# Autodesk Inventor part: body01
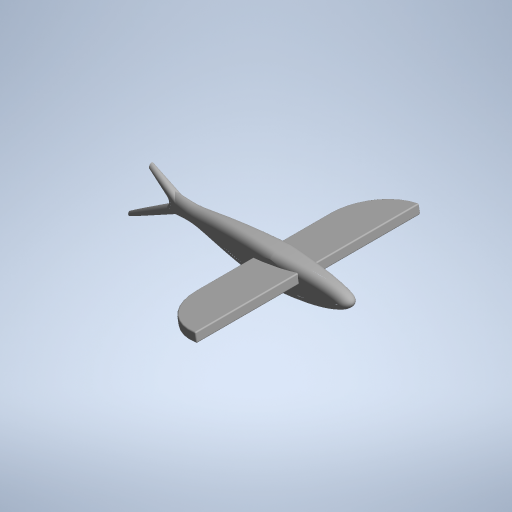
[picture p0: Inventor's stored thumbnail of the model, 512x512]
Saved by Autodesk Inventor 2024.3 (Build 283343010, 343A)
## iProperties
Created: 2018-12
Part Number: body01
Material: 一般
Document SubType Name: モデリング
Designer: Kikut
Appearance: 一般
Author: Kikut
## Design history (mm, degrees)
sketch "スケッチ1"
  geometry: L1 (-60, 8)-(-60, -10); 8 further points
  constraints: 2 end point, 9 other
  dimensions: "d0" = 100 distance of point (0, 0) point (100, 0); "d1" = 60 horizontal distance of L1.end point (0, 0); "d2" = 0 horizontal distance of L1.end L1.start; "d3" = 0 horizontal distance of point (-38, -8) point (-38, 6); "d4" = 14 horizontal distance of point (-14, -12) point (0, 0); "d5" = 24 horizontal distance of point (-38, -8) point (-14, -12); "d6" = 20 horizontal distance of point (-20, 8) point (0, 0); "d7" = 30 horizontal distance of point (70, -14) point (100, 0); "d8" = 34 horizontal distance of point (100, 0) point (66, 10); "d9" = 10 vertical distance of point (100, 0) point (66, 10); "d10" = 0 vertical distance of point (0, 0) point (100, 0); "d11" = 14 vertical distance of point (70, -14) point (100, 0); "d12" = 8 vertical distance of point (0, 0) point (-20, 8); "d13" = 12 vertical distance of point (-14, -12) point (0, 0); "d14" = 8 vertical distance of point (-38, -8) point (0, 0); "d15" = 10 vertical distance of L1.end point (0, 0); "d16" = 8 vertical distance of L1.start point (0, 0); "d17" = 6 vertical distance of point (-38, 6) point (0, 0)
extrude "押し出し1" new body sketch "スケッチ1" stored distance "d29" = 20; taper "d30" = 0 deg
sketch "スケッチ6"
  geometry: L1 (-18, 20)-(0, 20); L2 (0, 20)-(0, 0); L3 (0, 0)-(-18, 0); L4 (-18, 0)-(-18, 20); 1 further point
  constraints: 8 end point, 2 parallel, 1 horizontal, 1 perpendicular
extrude "押し出し6" join sketch "スケッチ6" distance "d59" = 40; taper "d60" = 30 deg
sketch "スケッチ7"
  geometry: L1 (-50, 11)-(30, 11); L2 (30, 11)-(30, 51); L3 (30, 51)-(-50, 51); L4 (-50, 51)-(-50, 11); 1 further point
  constraints: 8 end point, 2 parallel, 1 horizontal, 1 perpendicular
  dimensions: "d61" = 40 distance from line of point (-10, 10) L4; "d62" = 80 distance of L2.end L3.end; "d63" = 40 distance of L3.end L1.start; "d64" = 1 distance from line of L1 point (-10, 10)
extrude "押し出し7" cut sketch "スケッチ7" extent not by distance; stored distance "d65" = 40; taper "d66" = -4 deg
sketch "スケッチ8"
  geometry: L1 (-50, -31)-(30, -31); L2 (30, -31)-(30, 9); L3 (30, 9)-(-50, 9); L4 (-50, 9)-(-50, -31); 1 further point
  constraints: 8 end point, 2 parallel, 1 horizontal, 1 perpendicular
  dimensions: "d67" = 1 distance from line of point (-10, 10) L3; "d68" = 40 distance of L3.end L1.start; "d69" = 40 distance from line of point (-10, 10) L4; "d70" = 80 distance of L1.start L1.end
extrude "押し出し8" cut sketch "スケッチ8" extent not by distance; stored distance "d71" = 40; taper "d72" = -4 deg
sketch "スケッチ9" dims "d130" = 3
  geometry: L1 (-40, 30)-(20, 30); L2 (20, 30)-(20, 60); L3 (20, 60)-(-40, 60); L4 (-40, 60)-(-40, 30); 1 further point
  constraints: 8 end point, 2 parallel, 1 horizontal, 1 perpendicular
  dimensions: "d73" = 20 distance from line of L1 point (-10, 10); "d74" = 30 distance of L3.end L1.start; "d75" = 30 distance from line of point (-10, 10) L4; "d76" = 60 distance of L2.end L3.end
extrude "押し出し9" cut sketch "スケッチ9" extent not by distance; stored distance "d77" = 0; taper "d78" = 4 deg
sketch "スケッチ10"
  geometry: L1 (-40, -40)-(20, -40); L2 (20, -40)-(20, -10); L3 (20, -10)-(-40, -10); L4 (-40, -10)-(-40, -40); L5 (-41.094, 9)-(23.094, 9) reference; 3 further points
  constraints: 8 end point, 2 parallel, 1 horizontal, 1 perpendicular
  dimensions: "d80" = 30 distance of L3.end L1.start; "d81" = 30 distance from line of point (-10, 10) L4; "d82" = 60 distance of L1.start L1.end; "d85" = 20 distance from line of L3 point (-10, 10)
extrude "押し出し10" cut sketch "スケッチ10" extent not by distance; stored distance "d83" = 0; taper "d84" = 4 deg
fillet "フィレット8" dims "d100" = 6
fillet "フィレット9" dims "d101" = 6
sketch "スケッチ14"
  geometry: L1 (62, 1)-(62, -3); L2 (62, -3)-(112.078, -35); L3 (112.078, -35)-(112.078, 37); L4 (112.078, 37)-(62, 1); L5 (112.078, 37)-(112.078, 47); L6 (112.078, 47)-(80.078, 23.996); L7 (80.078, 23.996)-(80.078, 13.996); L8 (80.078, 13.996)-(112.078, 37); 1 further point
  constraints: 16 end point, 2 parallel, 2 vertical, 1 collinear, 1 point on line
  dimensions: "d119" = 62 distance from line of L1 point (0, 0); "d120" = 1 vertical distance of point (0, 0) L1.start; "d121" = 3 vertical distance of L1.end point (0, 0); "d122" = 36 vertical distance of L3.end L1.start; "d123" = 32 vertical distance of L2.end L1.end; "d124" = 10 distance of L3.end L5.end; "d125" = 10 distance of L6.end L7.end; "d126" = 32 distance between parallel lines of L5 L7
extrude "押し出し14" cut sketch "スケッチ14" extent not by distance; stored distance "d127" = 40; taper "d128" = 0 deg
fillet "フィレット14" dims "d129" = 4
fillet "フィレット15" dims "d130" = 3
fillet "フィレット16" dims "d131" = 2
sketch "スケッチ15"
  geometry: L1 (19.609, 0.466)-(59.002, 7.412); L2 (59.002, 7.412)-(60.391, -0.466); L3 (60.391, -0.466)-(20.998, -7.412); L4 (20.998, -7.412)-(19.609, 0.466); L5 (19.609, 0.466)-(60.391, -0.466); L6 (59.002, 7.412)-(20.998, -7.412); L7 (171.819, 0)-(-145.303, 0) reference; 4 further points
  constraints: 12 end point, 4 midpoint, 2 parallel, 1 perpendicular
  dimensions: "d132" = 40 distance of L1.start L1.end; "d133" = 40 distance of point (0, 0) point (40, 0); "d134" = 10 deg angle of L7 L3; "d135" = 0 vertical distance of point (0, 0) point (40, 0); "d136" = 8 distance of L1.end L2.end
extrude "押し出し15" join sketch "スケッチ15" stored distance "d137" = 200; taper "d138" = 0 deg
fillet "フィレット17" dims "d139" = 40
fillet "フィレット18" dims "d140" = 1
node "ソリッド1"
node "ソリッド ボディ"
node "サーフェス ボディ"
